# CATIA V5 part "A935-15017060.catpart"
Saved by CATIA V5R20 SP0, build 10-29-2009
Part number: A935-15017060
Source: Unknown
Property "A": "110.000"
Property "ARTICLENO": "A935-15017060"
Property "B": "30.000"
Property "BOMINFO": "A935-15017060"
Property "CODE": "A935-15017060"
Property "L": "170.000"
Property "L1": "127.860"
Property "LINA": "A935-15017060"
Property "NB": "A935-15017060"
Property "NBSYN": "$CODE."
Property "NN": "A935"
Property "NT": "VDI 3357 H-Type Cam Drivers, steel (16MnCr5)"
Property "SUPPLIER": "CF"
Property "T": "60.000"
Property "W": "150.000"
Bounding box of the stored display mesh (mm): x 0 to 170, y 0 to 60, z -150 to 0
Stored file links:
  C:\Users\Utente\Desktop\3D files A935\A935-15017060.catpart
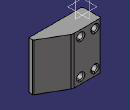
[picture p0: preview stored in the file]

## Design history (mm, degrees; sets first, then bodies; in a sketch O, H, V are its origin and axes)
Body1 "Geometry.1" (main body)
  Solid1 "A935-15017060.catpart": solid without history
